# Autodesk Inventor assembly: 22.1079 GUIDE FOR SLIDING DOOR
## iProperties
Created: 2007-05
Part Number: 22.1079 GUIDE FOR SLIDING DOOR
Document SubType Name: Assembly
Designer: Andy Moles
Mass: 11.3955 g
Surface Area: 51.2919 cm^2
Volume: 11.0639 cm^3
Density: 1.02997 g/cm^3
Author: Andy Moles
